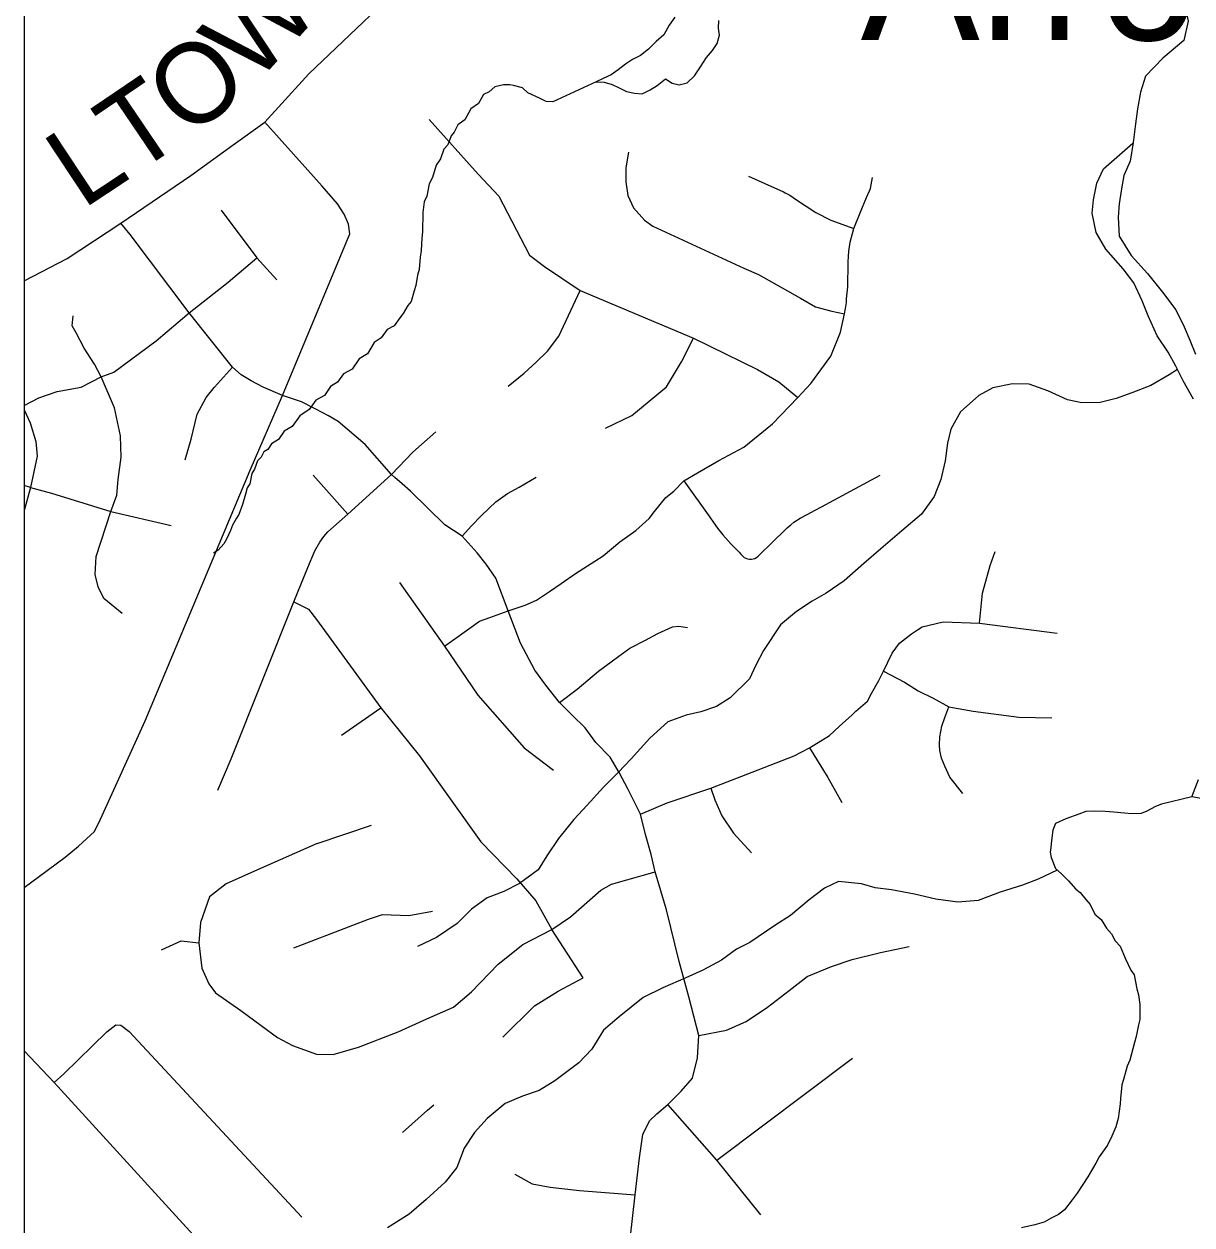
# Model space of a CAD drawing. Extents: x 0 to 34, y 0 to 22.
# Drawn here: x 2.1 to 2.928, y 18.554 to 19.406 of the extents above; entities that cross this region are included whole.
import ezdxf

# ---------------------------------------------------------------- set-up
doc = ezdxf.new("R2010")
doc.units = 0
for name, color, linetype in [('GM_X_Corporation', 7, 'Continuous'), ('GM_X_County_Road', 7, 'Continuous'), ('GM_X_County_Road_Text', 7, 'Continuous'), ('GM_X_Minor_Lake', 7, 'Continuous'), ('GM_X_Minor_Lake_Text', 7, 'Continuous'), ('GM_X_Minor_River', 7, 'Continuous'), ('GM_X_Township_Road', 7, 'Continuous'), ('SH_Data', 7, 'Continuous')]:
    doc.layers.add(name, color=color, linetype=linetype)

msp = doc.modelspace()

# ---------------------------------------------------------------- linework, layer by layer
at = {"layer": 'GM_X_Corporation'}
msp.add_lwpolyline([(2.1, 20.9), (2.1, 16.09335)], dxfattribs=at)
at = {"layer": 'GM_X_County_Road'}
msp.add_lwpolyline([(2.1, 19.22381), (2.13057, 19.23979), (2.16872, 19.26464), (2.21827, 19.29865), (2.24832, 19.32032), (2.27077, 19.33641), (2.3018, 19.37055), (2.3839, 19.44898), (2.44144, 19.50579), (2.47044, 19.53406), (2.4845, 19.55121), (2.51948, 19.59407), (2.56749, 19.65957), (2.58052, 19.67877), (2.58326, 19.68278)], dxfattribs=at)
at = {"layer": 'GM_X_Minor_Lake'}
msp.add_lwpolyline([(2.56137, 19.41073), (2.55749, 19.4051), (2.55359, 19.39832), (2.54821, 19.39346), (2.54281, 19.38822), (2.53705, 19.38375), (2.53131, 19.3808), (2.52632, 19.37746), (2.52132, 19.37336), (2.51633, 19.37001), (2.5106, 19.36744), (2.50562, 19.36485), (2.51132, 19.36477), (2.517, 19.36317), (2.52191, 19.36082), (2.52719, 19.35808), (2.53287, 19.35686), (2.53818, 19.3564), (2.54393, 19.35936), (2.54891, 19.36232), (2.55468, 19.36717), (2.55957, 19.36406), (2.5645, 19.36285), (2.57022, 19.36429), (2.57523, 19.36915), (2.5795, 19.37554), (2.58377, 19.38231), (2.58802, 19.38718), (2.59151, 19.39207), (2.59312, 19.39812), (2.59243, 19.40307), (2.5925, 19.40838)], dxfattribs=at)
at = {"layer": 'GM_X_Minor_River'}
for points in [[(2.91461, 19.44272), (2.91521, 19.4332), (2.92226, 19.4232), (2.92542, 19.40794), (2.92214, 19.39431), (2.90746, 19.38164), (2.89506, 19.36893), (2.89144, 19.35759), (2.88933, 19.34584), (2.88801, 19.33522), (2.88625, 19.32195)], [(2.50562, 19.36485), (2.47501, 19.35088), (2.47006, 19.35097), (2.46555, 19.35333), (2.45725, 19.35728), (2.4535, 19.36076), (2.44707, 19.3624), (2.44441, 19.36283), (2.43985, 19.36291), (2.43375, 19.36149), (2.42988, 19.35776), (2.42567, 19.35593), (2.42214, 19.34952), (2.41675, 19.34582), (2.41244, 19.3379), (2.40744, 19.33457), (2.40507, 19.32928), (2.40274, 19.32666), (2.40035, 19.32024), (2.39764, 19.31724), (2.39525, 19.31044), (2.39213, 19.30593), (2.3897, 19.29722), (2.38734, 19.2927), (2.38567, 19.28398), (2.3837, 19.27983), (2.38282, 19.27224), (2.38258, 19.25855), (2.38213, 19.25399), (2.3816, 19.24525), (2.38076, 19.2407), (2.38023, 19.23196), (2.37902, 19.2278), (2.37776, 19.22059), (2.37656, 19.21681), (2.37453, 19.20924), (2.3722, 19.20624), (2.36868, 19.20059), (2.36635, 19.19759), (2.36245, 19.19195), (2.35747, 19.18938), (2.35318, 19.18337), (2.34818, 19.18003), (2.34349, 19.17213), (2.33772, 19.16842), (2.33266, 19.16129), (2.32652, 19.15797), (2.32224, 19.15196), (2.31724, 19.149), (2.31295, 19.14261), (2.30682, 19.1393), (2.30214, 19.13253), (2.2956, 19.12808), (2.29015, 19.12057), (2.28439, 19.11725), (2.28049, 19.11123), (2.2755, 19.10827), (2.27277, 19.10414), (2.27008, 19.10266), (2.26812, 19.09889), (2.26541, 19.09628), (2.26341, 19.09023), (2.26146, 19.08722), (2.26019, 19.08001), (2.25824, 19.077), (2.25702, 19.07246), (2.255, 19.06527), (2.25222, 19.05809), (2.25066, 19.05546), (2.24791, 19.05056), (2.24633, 19.04678), (2.24356, 19.04075), (2.2416, 19.03736), (2.23773, 19.03286), (2.23427, 19.03064)], [(2.92911, 19.13987), (2.92173, 19.15292), (2.91658, 19.16328), (2.91105, 19.17326), (2.90326, 19.1848), (2.89704, 19.19897), (2.89266, 19.20969), (2.8868, 19.22234), (2.87936, 19.23235), (2.86705, 19.24625), (2.86003, 19.25816), (2.85723, 19.2719), (2.85815, 19.28138), (2.86064, 19.29312), (2.86538, 19.30331), (2.88618, 19.32147)], [(2.88625, 19.32195), (2.88412, 19.30868), (2.87976, 19.29849), (2.87807, 19.28902), (2.87636, 19.2784), (2.87582, 19.26891), (2.87634, 19.2556), (2.88485, 19.24176), (2.89642, 19.22901), (2.90723, 19.2159), (2.91652, 19.20319), (2.9224, 19.19131), (2.92641, 19.18173), (2.93043, 19.17178)], [(2.91778, 19.16086), (2.91191, 19.15728), (2.89884, 19.14952), (2.88544, 19.14443), (2.87433, 19.14045), (2.86287, 19.13761), (2.84994, 19.13745), (2.8397, 19.13953), (2.82573, 19.14586), (2.8125, 19.15065), (2.80071, 19.15086), (2.78696, 19.14806), (2.77698, 19.14253), (2.76384, 19.13097), (2.75716, 19.11855), (2.7547, 19.10871), (2.75296, 19.09619), (2.75007, 19.08294), (2.74529, 19.07086), (2.73632, 19.05847), (2.72242, 19.04654), (2.70736, 19.03388), (2.69539, 19.02345), (2.68148, 19.01115), (2.66876, 19.00225), (2.65878, 18.99672), (2.64762, 18.98931), (2.63642, 18.98), (2.6243, 18.96159), (2.6188, 18.95142), (2.61444, 18.94161), (2.60051, 18.92817), (2.59089, 18.92188), (2.5798, 18.91827), (2.56948, 18.91579), (2.55647, 18.91107), (2.54371, 18.89951), (2.53052, 18.88492), (2.52122, 18.8752), (2.51076, 18.86473), (2.49913, 18.85201), (2.48982, 18.84191), (2.47893, 18.82842), (2.47073, 18.81602), (2.46447, 18.80624), (2.45137, 18.79659), (2.44023, 18.7907), (2.42836, 18.78635), (2.41719, 18.77818), (2.40712, 18.76809), (2.39249, 18.75808), (2.37906, 18.75185)], [(2.94127, 18.85569), (2.92799, 18.85782), (2.93277, 18.87028)], [(2.92799, 18.85782), (2.90647, 18.85264), (2.90226, 18.85119), (2.89612, 18.84787), (2.89191, 18.84605), (2.88506, 18.84579), (2.88013, 18.84625), (2.87254, 18.84715), (2.8695, 18.8472), (2.86646, 18.84763), (2.85886, 18.84777), (2.85277, 18.84749), (2.8478, 18.84568), (2.83862, 18.84242), (2.83134, 18.83912), (2.82936, 18.83421), (2.82848, 18.827), (2.82801, 18.82206), (2.82757, 18.81865), (2.82827, 18.81483), (2.83118, 18.80717), (2.83531, 18.80368), (2.84054, 18.79826), (2.84576, 18.79246), (2.84876, 18.79013), (2.85286, 18.78511)], [(2.83251, 18.80604), (2.81893, 18.79966), (2.80782, 18.7953), (2.79213, 18.79025), (2.77644, 18.78444), (2.76196, 18.78317), (2.7464, 18.78534), (2.73124, 18.78903), (2.71493, 18.79198), (2.70354, 18.79332), (2.6937, 18.79615), (2.67737, 18.79796), (2.6674, 18.79319), (2.65661, 18.78501), (2.64347, 18.77384), (2.63232, 18.76681), (2.6146, 18.75458), (2.60501, 18.7498), (2.5946, 18.742), (2.58116, 18.73501), (2.56928, 18.72952), (2.5528, 18.72259), (2.53898, 18.71561), (2.522, 18.70183), (2.5108, 18.69253), (2.50258, 18.67899), (2.49328, 18.66927), (2.47631, 18.65664), (2.46516, 18.64961), (2.4533, 18.64563), (2.44103, 18.64053), (2.42829, 18.62972), (2.41937, 18.62), (2.41195, 18.60872), (2.40676, 18.59513), (2.39859, 18.58463), (2.38506, 18.57232), (2.37308, 18.56188), (2.3577, 18.55227)], [(2.85286, 18.78511), (2.85584, 18.78163), (2.85915, 18.77473), (2.86365, 18.77085), (2.86734, 18.7647), (2.87108, 18.76083), (2.87366, 18.75584), (2.87701, 18.75198), (2.88067, 18.74354), (2.88471, 18.7351), (2.88694, 18.73164), (2.88905, 18.72172), (2.89012, 18.71751), (2.89114, 18.71065), (2.89096, 18.7), (2.89014, 18.69621), (2.88848, 18.68787), (2.88727, 18.68371), (2.88401, 18.67122), (2.88204, 18.66706), (2.8796, 18.6576), (2.8784, 18.65382), (2.87747, 18.64394), (2.87703, 18.64015), (2.87571, 18.6299), (2.87409, 18.62384), (2.87132, 18.61742), (2.86817, 18.61101), (2.86233, 18.60275), (2.85997, 18.59822), (2.85762, 18.59408), (2.8541, 18.58844), (2.84668, 18.57678), (2.84319, 18.57227), (2.83774, 18.56514), (2.8335, 18.56179), (2.82814, 18.55922), (2.82315, 18.55627), (2.81665, 18.55448), (2.80711, 18.55236)]]:
    msp.add_lwpolyline(points, dxfattribs=at)
at = {"layer": 'GM_X_Township_Road'}
for p, q in [((2.3049, 19.08614), (2.32948, 19.05848)), ((2.10467, 19.07736), (2.1, 19.07883)), ((2.32518, 18.90155), (2.35285, 18.92099)), ((2.23742, 18.86277), (2.24676, 18.88495)), ((2.30779, 18.82491), (2.3464, 18.83787)), ((2.29134, 18.75093), (2.33319, 18.76688)), ((2.59115, 18.60028), (2.68744, 18.67258))]:
    msp.add_line(p, q, dxfattribs=at)
for points in [[(2.1, 18.79366), (2.11102, 18.80166), (2.12919, 18.81524), (2.13866, 18.82299), (2.14987, 18.83335), (2.15421, 18.84204), (2.18598, 18.91185), (2.2604, 19.08957), (2.28319, 19.14249), (2.33107, 19.25723), (2.32993, 19.2641), (2.32707, 19.27111), (2.32235, 19.27854), (2.31147, 19.29099), (2.27077, 19.33641)], [(2.38723, 19.33826), (2.42186, 19.29941), (2.43655, 19.28397), (2.45841, 19.24204), (2.469, 19.23394), (2.49433, 19.21697), (2.57468, 19.18328), (2.61996, 19.16099), (2.63517, 19.15211), (2.64849, 19.14117)], [(2.52864, 19.31519), (2.52663, 19.30403), (2.52663, 19.29416), (2.52809, 19.28447), (2.53212, 19.27551), (2.53979, 19.26692), (2.54583, 19.26253), (2.61037, 19.23291), (2.62061, 19.22834), (2.6506, 19.21152), (2.6612, 19.2053), (2.67271, 19.20226), (2.68159, 19.20051)], [(2.39813, 18.96473), (2.4088, 18.97241), (2.41541, 18.9771), (2.42288, 18.98244), (2.43013, 18.98521), (2.44321, 18.9899), (2.45529, 18.99374), (2.4634, 18.99737), (2.47257, 19.00355), (2.48089, 19.00931), (2.49091, 19.01634), (2.51053, 19.02893), (2.52231, 19.03883), (2.5337, 19.04674), (2.5433, 19.05532), (2.54708, 19.06027), (2.55494, 19.07016), (2.56061, 19.07481), (2.56783, 19.08197), (2.57748, 19.08762), (2.59261, 19.09634), (2.61035, 19.10594), (2.63071, 19.12252), (2.64849, 19.14117), (2.65776, 19.15103), (2.67198, 19.17036), (2.6789, 19.18747), (2.68159, 19.20051), (2.68234, 19.20415), (2.68301, 19.2085), (2.68306, 19.21097), (2.68396, 19.21964), (2.68396, 19.22474), (2.68424, 19.2315), (2.68432, 19.23742), (2.68479, 19.24483), (2.68578, 19.25125), (2.68824, 19.26096), (2.69285, 19.27209), (2.6973, 19.28296), (2.69939, 19.28775), (2.7001, 19.28938), (2.70158, 19.29712)], [(2.61367, 19.2981), (2.62996, 19.29086), (2.63577, 19.28813), (2.63836, 19.28691), (2.6396, 19.28627), (2.64281, 19.2846), (2.64774, 19.28131), (2.66141, 19.27242), (2.67211, 19.26682), (2.68824, 19.26096)], [(2.2398, 19.27395), (2.26496, 19.24005), (2.27917, 19.22458)], [(2.28319, 19.14249), (2.26958, 19.14855), (2.26115, 19.15284), (2.25405, 19.15713), (2.24769, 19.1626), (2.21704, 19.20104), (2.17523, 19.2568), (2.16872, 19.26464)], [(2.1, 19.13545), (2.11056, 19.14082), (2.12345, 19.1454), (2.14048, 19.14852), (2.15469, 19.15566), (2.16371, 19.15912), (2.19364, 19.18141), (2.21704, 19.20104), (2.24465, 19.22302), (2.26496, 19.24005)], [(2.44328, 19.14922), (2.45449, 19.15844), (2.4632, 19.16616), (2.47117, 19.17388), (2.47914, 19.18459), (2.48761, 19.20277), (2.49433, 19.21697)], [(2.16965, 18.98784), (2.15664, 18.99856), (2.15254, 19.00677), (2.15049, 19.01567), (2.15117, 19.02844), (2.16144, 19.06037), (2.16577, 19.07178), (2.16668, 19.08295), (2.16896, 19.09892), (2.16828, 19.11397), (2.16408, 19.13386), (2.15469, 19.15566), (2.14987, 19.1648), (2.14269, 19.17617), (2.13686, 19.18693), (2.13402, 19.19186), (2.13492, 19.19904)], [(2.51215, 19.11945), (2.53086, 19.12833), (2.55559, 19.14862), (2.56605, 19.16637), (2.57468, 19.18328)], [(2.21422, 19.09697), (2.21849, 19.11157), (2.22271, 19.12932), (2.22908, 19.141), (2.23515, 19.14834), (2.24769, 19.1626)], [(2.52645, 18.51495), (2.53323, 18.57561), (2.53633, 18.60199), (2.53872, 18.61844), (2.54345, 18.6281), (2.54859, 18.63323), (2.5565, 18.63987), (2.56579, 18.64928), (2.57402, 18.65853), (2.57744, 18.67292), (2.57847, 18.68868), (2.57128, 18.7161), (2.56441, 18.74113), (2.55551, 18.77778), (2.54753, 18.80482), (2.54462, 18.81713), (2.54058, 18.83123), (2.5371, 18.8457), (2.52812, 18.86365), (2.52204, 18.87529), (2.51547, 18.88617), (2.50534, 18.89655), (2.49775, 18.90693), (2.48864, 18.91578), (2.47953, 18.92489), (2.46991, 18.93704), (2.46207, 18.94767), (2.45194, 18.9669), (2.44321, 18.9899), (2.43447, 19.01289), (2.42755, 19.02304), (2.42116, 19.03105), (2.41059, 19.04271), (2.39842, 19.05088), (2.37393, 19.07477), (2.36802, 19.07985), (2.36294, 19.08436), (2.36055, 19.08652), (2.34189, 19.10774), (2.32282, 19.12415), (2.31586, 19.128), (2.30699, 19.13273), (2.29664, 19.13805), (2.28319, 19.14249)], [(2.1, 19.13231), (2.10446, 19.12319), (2.10844, 19.1099), (2.10943, 19.0996), (2.10467, 19.07736), (2.1, 19.0611)], [(2.24676, 18.88495), (2.29139, 18.99627), (2.30126, 19.02046), (2.30626, 19.03243), (2.30962, 19.0385), (2.31267, 19.0426), (2.31542, 19.04578), (2.32948, 19.05848), (2.36055, 19.08652), (2.3757, 19.10245), (2.39201, 19.11675)], [(2.56783, 19.08197), (2.58614, 19.0562), (2.58885, 19.05254), (2.59174, 19.04842), (2.59355, 19.04605), (2.5954, 19.04363), (2.59942, 19.03915), (2.60138, 19.03714), (2.60403, 19.03441), (2.60703, 19.03133), (2.6083, 19.03002), (2.60965, 19.02864), (2.61065, 19.02777), (2.61179, 19.0271), (2.61302, 19.02663), (2.61432, 19.02638), (2.61564, 19.02636), (2.61819, 19.02701), (2.61934, 19.02766), (2.62037, 19.02849), (2.62173, 19.02981), (2.6241, 19.03212), (2.628, 19.03592), (2.63328, 19.04106), (2.63701, 19.04469), (2.64111, 19.04867), (2.64359, 19.05092), (2.64577, 19.05265), (2.65025, 19.05553), (2.65533, 19.05826), (2.6608, 19.06119), (2.66536, 19.06364), (2.67408, 19.06832), (2.70698, 19.08599)], [(2.10467, 19.07736), (2.11947, 19.07337), (2.16144, 19.06037), (2.20432, 19.05033)], [(2.41059, 19.04271), (2.41727, 19.0501), (2.42415, 19.05716), (2.42965, 19.06266), (2.43456, 19.06718), (2.4428, 19.07307), (2.45106, 19.07759), (2.46304, 19.08466)], [(2.77732, 18.98118), (2.7795, 19.00244), (2.78495, 19.02207), (2.78846, 19.03182)], [(2.36621, 19.00983), (2.39813, 18.96473), (2.42165, 18.92995), (2.45452, 18.89259), (2.47547, 18.87687)], [(2.29139, 18.99627), (2.30162, 18.99095), (2.30728, 18.98375), (2.35285, 18.92099), (2.38033, 18.88698), (2.42388, 18.82601), (2.44928, 18.79985), (2.46275, 18.78413), (2.47428, 18.76379)], [(2.47953, 18.92489), (2.49213, 18.9344), (2.50725, 18.94707), (2.52174, 18.9577), (2.52951, 18.96337), (2.54051, 18.96903), (2.54941, 18.97372), (2.55976, 18.97841), (2.56429, 18.97906), (2.57044, 18.97809)], [(2.68704, 18.91616), (2.68978, 18.91865), (2.6981, 18.92589), (2.70118, 18.93174), (2.70596, 18.94038), (2.70935, 18.947), (2.71551, 18.95979), (2.72075, 18.96688), (2.72908, 18.97351), (2.73339, 18.97628), (2.73678, 18.97859), (2.75157, 18.98214), (2.77732, 18.98118), (2.83238, 18.9741)], [(2.70935, 18.947), (2.7243, 18.93929), (2.73385, 18.93313), (2.74449, 18.92789), (2.75573, 18.92167), (2.77299, 18.91865), (2.80535, 18.91448), (2.82877, 18.91402)], [(2.5371, 18.8457), (2.55594, 18.85362), (2.58696, 18.86416), (2.62057, 18.87705), (2.64601, 18.8869), (2.65685, 18.89263), (2.67113, 18.90138), (2.67791, 18.90786), (2.68704, 18.91616)], [(2.76559, 18.86039), (2.75635, 18.87195), (2.75281, 18.87965), (2.75049, 18.88536), (2.74926, 18.89091), (2.74911, 18.89492), (2.74926, 18.90046), (2.7508, 18.90801), (2.75281, 18.91418), (2.75573, 18.92167)], [(2.65685, 18.89263), (2.66991, 18.8716), (2.67972, 18.85387)], [(2.58696, 18.86416), (2.58987, 18.85578), (2.59476, 18.84455), (2.60288, 18.83217), (2.61565, 18.81826)], [(2.30779, 18.82491), (2.26544, 18.80623), (2.24327, 18.79627), (2.23156, 18.78705), (2.22509, 18.76887), (2.22384, 18.75442), (2.22608, 18.73649), (2.23107, 18.72528), (2.2358, 18.71905), (2.25373, 18.70634), (2.26818, 18.69588), (2.27964, 18.68717), (2.29035, 18.68169), (2.30729, 18.67545), (2.31924, 18.67521), (2.33718, 18.68044), (2.36515, 18.69122)], [(2.36515, 18.69122), (2.38563, 18.70043), (2.40442, 18.7087), (2.41735, 18.71973), (2.43618, 18.73933), (2.45366, 18.75324), (2.47428, 18.76379), (2.48746, 18.77293), (2.50882, 18.79174), (2.51643, 18.79609), (2.52742, 18.79919), (2.54753, 18.80482)], [(2.33319, 18.76688), (2.34416, 18.77111), (2.35412, 18.7746), (2.3728, 18.77385), (2.38949, 18.77684)], [(2.43955, 18.68758), (2.46192, 18.70965), (2.47869, 18.72009), (2.49634, 18.72966), (2.47428, 18.76379)], [(2.19744, 18.74944), (2.21139, 18.75592), (2.22384, 18.75442)], [(2.57847, 18.68868), (2.598, 18.69245), (2.61205, 18.69862), (2.62713, 18.7089), (2.64255, 18.72055), (2.65523, 18.73049), (2.67236, 18.73768), (2.6871, 18.74248), (2.70731, 18.74762), (2.72753, 18.75173)], [(2.12147, 18.65525), (2.12831, 18.66145), (2.15881, 18.6913), (2.1651, 18.69629), (2.1687, 18.69602), (2.17443, 18.69158), (2.29691, 18.55977)], [(2.1, 18.67791), (2.12147, 18.65525), (2.24719, 18.51748), (2.28545, 18.47695), (2.32205, 18.43572), (2.32861, 18.42799)], [(2.36837, 18.61998), (2.38605, 18.63569), (2.39057, 18.63963)], [(2.62233, 18.56156), (2.59115, 18.60028), (2.5565, 18.63987)], [(2.44792, 18.59034), (2.46026, 18.58349), (2.47293, 18.58109), (2.49384, 18.57869), (2.53323, 18.57561)]]:
    msp.add_lwpolyline(points, dxfattribs=at)
at = {"layer": 'SH_Data'}
msp.add_line((2.1, 20.9), (2.1, 14.1), dxfattribs=at)

# ---------------------------------------------------------------- texts
at = {"layer": 'GM_X_County_Road_Text'}
for s, rotation, p in [('W', 47.77041, (2.26345, 19.3619)), ('O', 37.5863, (2.21573, 19.32394)), ('T', 34.11933, (2.1775, 19.2979)), ('L', 33.48517, (2.14148, 19.27407))]:
    msp.add_text(s, height=0.05682, rotation=rotation, dxfattribs=at).set_placement(p)
at = {"layer": 'GM_X_Minor_Lake_Text'}
msp.add_text('Arrowhead', height=0.094696, rotation=0.00043, dxfattribs=at).set_placement((2.69315, 19.39456))

doc.saveas('drawing.dxf')
